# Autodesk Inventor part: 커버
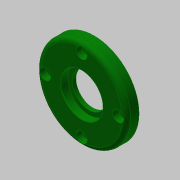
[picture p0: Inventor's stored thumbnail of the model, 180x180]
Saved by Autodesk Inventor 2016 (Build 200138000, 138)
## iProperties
Created: 2019-09
Part Number: 커버
Material: 알루미늄 6061
Document SubType Name: Modeling
Designer: mduedu
Density: 1 g/cm^3
Appearance: 진녹색
Author: mduedu
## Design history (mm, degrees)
sketch "스케치1"
  geometry: C1 r 32 at (0, 0); 1 further point
  constraints: 1 centre point, 1 coincident
  dimensions: "d0" = 64 diameter of C1
extrude "돌출1" new body sketch "스케치1" distance "d1" = 9; taper "d2" = 0 deg
sketch "스케치2"
  geometry: C1 r 21 at (0, 0); 1 further point
  constraints: 1 centre point, 1 coincident
  dimensions: "d3" = 42 diameter of C1
extrude "돌출2" join sketch "스케치2" distance "d4" = 3; taper "d5" = 0 deg
hole "구멍1" diameter "d8" = 24; stored, may be unused: countersink angle "d12" = 90 deg, drill point angle "d14" = 118 deg; dims "d6" = 10, "d7" = 10, "d9" = 6, "d10" = 30, "d11" = 5.2, "d13" = 8
hole "구멍2" diameter "d17" = 37; stored, may be unused: countersink angle "d21" = 90 deg, drill point angle "d23" = 0 deg; dims "d15" = 10, "d16" = 10, "d18" = 6, "d19" = 30, "d20" = 5.2, "d22" = 4
fillet "모깎기1" dims "d24" = 3
fillet "모깎기2" dims "d25" = 3
chamfer "모따기1" distance "d27" = 0.5; stored, may be unused: second distance "d28" = 2, angle "d29" = 30 deg
chamfer "모따기2" distance "d30" = 1; stored, may be unused: second distance "d31" = 2, angle "d32" = 30 deg
sketch "스케치3" dims "d33" = 52
  geometry: 3 further points
  constraints: 2 vertical alignment, 1 coincident, 2 other
hole "구멍3" sketch "스케치3" at (0, 26) diameter "d34" = 4.5; stored, may be unused: countersink angle "d38" = 90 deg, drill point angle "d40" = 0 deg; dims "d35" = 6, "d36" = 8, "d37" = 4.4, "d39" = 4
node "솔리드1"
pattern_circular "원형 패턴1" dims angle "d42" = 360 deg
